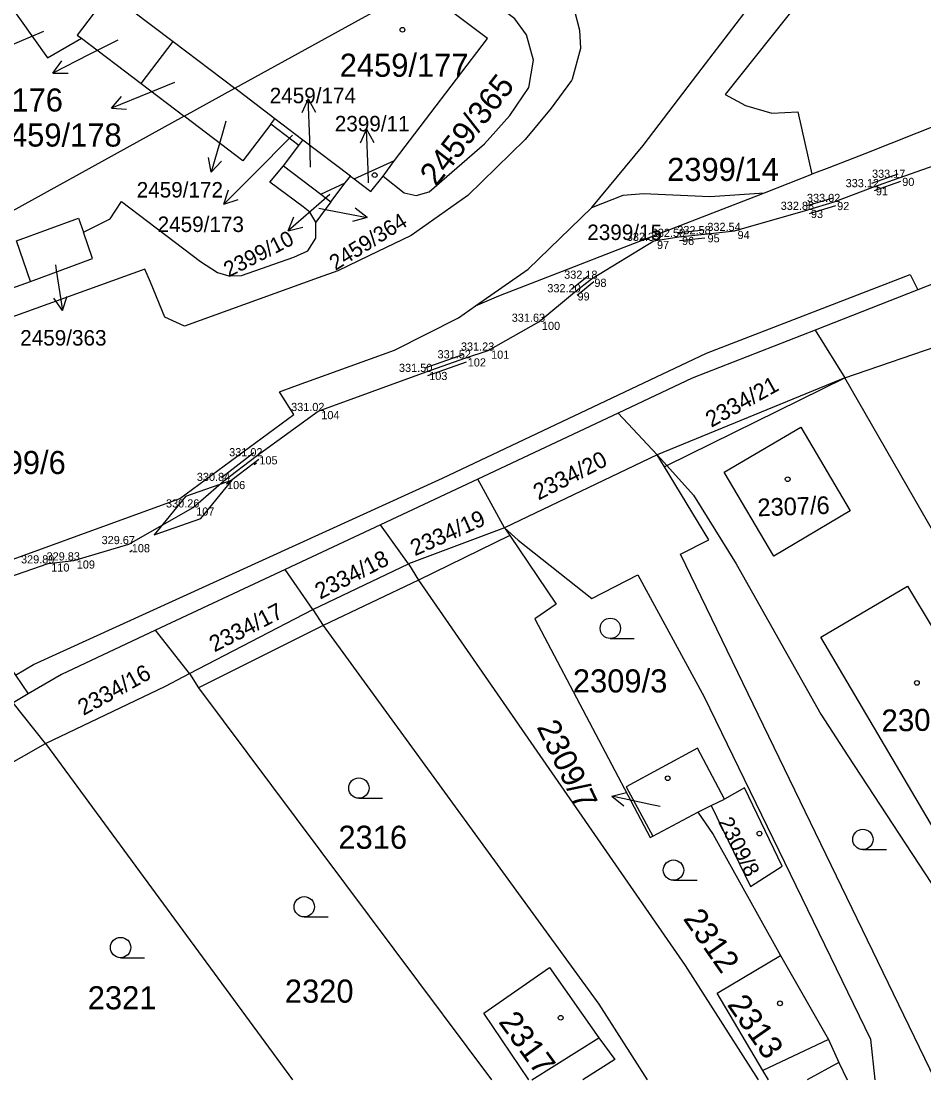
# Model space of a CAD drawing. Extents: x -606208 to -605570, y -1157873 to -1157573.
# Drawn here: x -605756.7 to -605690.3, y -1157764.5 to -1157686.5 of the extents above; entities that cross this region are included whole.
import ezdxf

# ---------------------------------------------------------------- set-up
doc = ezdxf.new("R2010")
doc.units = 0
for name, color, linetype in [('Vrstva 23', 7, 'Continuous'), ('Vrstva 30', 7, 'Continuous'), ('Vrstva 38', 7, 'Continuous'), ('Vrstva 58', 7, 'Continuous'), ('Vrstva 59', 7, 'Continuous'), ('Vrstva 60', 7, 'Continuous'), ('Vrstva 62', 7, 'Continuous'), ('Vrstva 7', 7, 'Continuous')]:
    doc.layers.add(name, color=color, linetype=linetype)

msp = doc.modelspace()

# ---------------------------------------------------------------- linework, layer by layer
at = {"layer": 'Vrstva 23'}
for p, q in [((-605739.593, -1157719.164), (-605739.429, -1157719.049)), ((-605748.587, -1157725.496), (-605748.751, -1157725.611))]:
    msp.add_line(p, q, dxfattribs=at)
msp.add_lwpolyline([(-605746.952, -1157724.345), (-605743.514, -1157723.148), (-605741.228, -1157720.315), (-605744.666, -1157721.512)], close=True, dxfattribs=at)
at = {"layer": 'Vrstva 30'}
msp.add_lwpolyline([(-605763.32, -1157729.43), (-605754.76, -1157726.45), (-605752.88, -1157726.23), (-605748.83, -1157725.03), (-605744.09, -1157722.33), (-605741.82, -1157720.38), (-605739.44, -1157718.56), (-605734.88, -1157715.23), (-605726.94, -1157712.35), (-605724.1, -1157711.35), (-605722.38, -1157710.78), (-605718.64, -1157708.66), (-605716.02, -1157706.49), (-605714.78, -1157705.49), (-605710.17, -1157702.7), (-605708.33, -1157702.41), (-605706.45, -1157702.21), (-605704.24, -1157701.97), (-605698.84, -1157700.42), (-605696.91, -1157699.84), (-605694.06, -1157698.75), (-605692.12, -1157698.06), (-605675.54, -1157692.21)], dxfattribs=at)
at = {"layer": 'Vrstva 38'}
for p, q in [((-605692.22, -1157697.78), (-605694.16, -1157698.47)), ((-605692.02, -1157698.34), (-605693.96, -1157699.03)), ((-605697, -1157699.55), (-605698.93, -1157700.13)), ((-605696.82, -1157700.13), (-605698.75, -1157700.71)), ((-605706.48, -1157701.91), (-605708.36, -1157702.11)), ((-605706.42, -1157702.51), (-605708.3, -1157702.71)), ((-605714.97, -1157705.26), (-605716.21, -1157706.26)), ((-605714.59, -1157705.72), (-605715.83, -1157706.72))]:
    msp.add_line(p, q, dxfattribs=at)
at = {"layer": 'Vrstva 60'}
for p, q in [((-605692.12, -1157698.06), (-605692.12, -1157698.06)), ((-605694.06, -1157698.75), (-605694.06, -1157698.75)), ((-605696.91, -1157699.84), (-605696.91, -1157699.84)), ((-605698.84, -1157700.42), (-605698.84, -1157700.42)), ((-605708.33, -1157702.41), (-605708.33, -1157702.41)), ((-605706.45, -1157702.21), (-605706.45, -1157702.21)), ((-605704.24, -1157701.97), (-605704.24, -1157701.97)), ((-605710.17, -1157702.7), (-605710.17, -1157702.7)), ((-605714.78, -1157705.49), (-605714.78, -1157705.49)), ((-605716.02, -1157706.49), (-605716.02, -1157706.49)), ((-605718.64, -1157708.66), (-605718.64, -1157708.66)), ((-605722.38, -1157710.78), (-605722.38, -1157710.78)), ((-605724.1, -1157711.35), (-605724.1, -1157711.35)), ((-605726.94, -1157712.35), (-605726.94, -1157712.35)), ((-605734.88, -1157715.23), (-605734.88, -1157715.23)), ((-605739.44, -1157718.56), (-605739.44, -1157718.56)), ((-605741.82, -1157720.38), (-605741.82, -1157720.38)), ((-605744.09, -1157722.33), (-605744.09, -1157722.33)), ((-605748.83, -1157725.03), (-605748.83, -1157725.03)), ((-605754.76, -1157726.45), (-605754.76, -1157726.45)), ((-605752.88, -1157726.23), (-605752.88, -1157726.23))]:
    msp.add_line(p, q, dxfattribs=at)
at = {"layer": 'Vrstva 62'}
for p, q in [((-605755.11, -1157687.29), (-605757.872, -1157688.463)), ((-605752.31, -1157687.79), (-605747.92, -1157691.12)), ((-605749.64, -1157687.93), (-605751.74, -1157688.99)), ((-605747.92, -1157691.12), (-605745.57, -1157688.03)), ((-605745.57, -1157688.03), (-605741.03, -1157691.47)), ((-605751.74, -1157688.99), (-605754.414, -1157690.352)), ((-605754.414, -1157690.352), (-605753.749, -1157689.452)), ((-605754.414, -1157690.352), (-605753.294, -1157690.344)), ((-605747.92, -1157691.12), (-605744.75, -1157693.52)), ((-605745.47, -1157691.04), (-605747.32, -1157691.8)), ((-605744.75, -1157693.52), (-605741.03, -1157691.47)), ((-605738.08, -1157693.71), (-605741.03, -1157691.47)), ((-605747.32, -1157691.8), (-605750.102, -1157692.924)), ((-605750.102, -1157692.924), (-605749.362, -1157692.085)), ((-605735.615, -1157692.251), (-605736.08, -1157693.269)), ((-605735.51, -1157695.25), (-605735.615, -1157692.251)), ((-605735.615, -1157692.251), (-605735.079, -1157693.234)), ((-605750.102, -1157692.924), (-605748.986, -1157693.013)), ((-605741.69, -1157693.9), (-605741.94, -1157694.77)), ((-605738.38, -1157694.11), (-605738.08, -1157693.71)), ((-605736.01, -1157695.28), (-605738.08, -1157693.71)), ((-605741.94, -1157694.77), (-605742.767, -1157697.655)), ((-605736.31, -1157695.68), (-605738.38, -1157694.11)), ((-605731.325, -1157694.481), (-605731.79, -1157695.499)), ((-605731.22, -1157697.48), (-605731.325, -1157694.481)), ((-605731.325, -1157694.481), (-605730.789, -1157695.464)), ((-605736.77, -1157694.93), (-605739.72, -1157697.88)), ((-605736.31, -1157695.68), (-605736.01, -1157695.28)), ((-605732.51, -1157697.94), (-605736.01, -1157695.28)), ((-605735.45, -1157697.27), (-605735.51, -1157695.25)), ((-605737.45, -1157697.18), (-605736.31, -1157695.68)), ((-605742.767, -1157697.655), (-605742.972, -1157696.554)), ((-605742.767, -1157697.655), (-605742.01, -1157696.83)), ((-605732.24, -1157698.14), (-605729.28, -1157696.78)), ((-605730.11, -1157697.93), (-605729.28, -1157696.78)), ((-605739.72, -1157697.88), (-605741.842, -1157700.002)), ((-605737.45, -1157697.18), (-605734.7, -1157699.27)), ((-605731.18, -1157698.43), (-605731.22, -1157697.48)), ((-605702.03, -1157699.16), (-605698.54, -1157697.8)), ((-605734.7, -1157699.27), (-605732.89, -1157698.44)), ((-605733.95, -1157699.84), (-605732.89, -1157698.44)), ((-605732.89, -1157698.44), (-605732.51, -1157697.94)), ((-605732.51, -1157697.94), (-605732.24, -1157698.14)), ((-605741.842, -1157700.002), (-605741.488, -1157698.94)), ((-605734.02, -1157699.3), (-605734.83, -1157700)), ((-605734.7, -1157699.27), (-605733.95, -1157699.84)), ((-605741.842, -1157700.002), (-605740.78, -1157699.648)), ((-605734.83, -1157700), (-605737.095, -1157701.969)), ((-605733.95, -1157699.84), (-605735.07, -1157701.32)), ((-605737.095, -1157701.969), (-605736.668, -1157700.934)), ((-605734.85, -1157700.29), (-605734.22, -1157700.41)), ((-605734.22, -1157700.41), (-605731.274, -1157700.983)), ((-605731.274, -1157700.983), (-605732.353, -1157701.283)), ((-605731.274, -1157700.983), (-605732.162, -1157700.3)), ((-605737.095, -1157701.969), (-605736.011, -1157701.69)), ((-605754.23, -1157704.47), (-605754.17, -1157704.87)), ((-605754.17, -1157704.87), (-605753.701, -1157707.834)), ((-605706.31, -1157710.96), (-605691.32, -1157705.17)), ((-605691.32, -1157705.17), (-605690.76, -1157706.31)), ((-605753.701, -1157707.834), (-605754.352, -1157706.923)), ((-605753.701, -1157707.834), (-605753.363, -1157706.767)), ((-605698.31, -1157709.27), (-605696.11, -1157712.79)), ((-605696.11, -1157712.79), (-605685.12, -1157708.99)), ((-605725.74, -1157720.17), (-605706.31, -1157710.96)), ((-605696.11, -1157712.79), (-605709.94, -1157718.45)), ((-605709.22, -1157719.25), (-605696.11, -1157712.79)), ((-605712.81, -1157715.38), (-605723.14, -1157720.24)), ((-605709.94, -1157718.45), (-605712.81, -1157715.38)), ((-605709.94, -1157718.45), (-605721.17, -1157723.83)), ((-605709.94, -1157718.45), (-605709.22, -1157719.25)), ((-605709.4, -1157719.34), (-605709.22, -1157719.25)), ((-605755.85, -1157733.9), (-605725.74, -1157720.17)), ((-605723.14, -1157720.24), (-605730.29, -1157723.6)), ((-605721.17, -1157723.83), (-605723.14, -1157720.24)), ((-605730.29, -1157723.6), (-605737.31, -1157726.9)), ((-605728.24, -1157726.49), (-605730.29, -1157723.6)), ((-605721.17, -1157723.83), (-605728.24, -1157726.49)), ((-605721.17, -1157723.83), (-605720.17, -1157724.75)), ((-605720.78, -1157724.4), (-605727.5, -1157727.68)), ((-605735.27, -1157729.85), (-605728.24, -1157726.49)), ((-605737.31, -1157726.9), (-605746.85, -1157731.37)), ((-605735.27, -1157729.85), (-605737.31, -1157726.9)), ((-605727.5, -1157727.68), (-605734.53, -1157731.01)), ((-605691.51, -1157728.12), (-605689.63, -1157731.27)), ((-605744.35, -1157734.56), (-605735.27, -1157729.85)), ((-605744.35, -1157734.56), (-605746.85, -1157731.37)), ((-605734.53, -1157731.01), (-605743.69, -1157735.6)), ((-605713.383, -1157731.98), (-605711.633, -1157731.98)), ((-605757.17, -1157734.67), (-605755.85, -1157733.9)), ((-605756.23, -1157736.06), (-605757.35, -1157736.71)), ((-605754.95, -1157739.7), (-605757.35, -1157736.71)), ((-605766.71, -1157746.36), (-605754.95, -1157739.7)), ((-605731.893, -1157743.74), (-605730.143, -1157743.74)), ((-605713.265, -1157743.596), (-605712.182, -1157743.314)), ((-605710.33, -1157744.22), (-605713.265, -1157743.596)), ((-605713.265, -1157743.596), (-605712.39, -1157744.294)), ((-605705.96, -1157744.28), (-605704.98, -1157743.8)), ((-605709.71, -1157744.35), (-605710.33, -1157744.22)), ((-605706.95, -1157744.76), (-605705.96, -1157744.28)), ((-605710.25, -1157746.53), (-605706.95, -1157744.76)), ((-605694.793, -1157747.52), (-605693.043, -1157747.52)), ((-605708.733, -1157749.78), (-605706.983, -1157749.78)), ((-605735.913, -1157752.48), (-605734.163, -1157752.48)), ((-605749.433, -1157755.48), (-605747.683, -1157755.48)), ((-605719.15, -1157764.47), (-605714.24, -1157761.37)), ((-605697.33, -1157761.51), (-605702.15, -1157763.78)), ((-605696.57, -1157763.2), (-605695.95, -1157764.47))]:
    msp.add_line(p, q, dxfattribs=at)
for points in [[(-605714.75, -1157700.25), (-605710.96, -1157695.68), (-605710.18, -1157694.65), (-605706.94, -1157690.4), (-605702.43, -1157684.48), (-605699.9, -1157681.15), (-605696.13, -1157676.2), (-605691.65, -1157670.31), (-605690.12, -1157670.1), (-605687.04, -1157672.45), (-605682.78, -1157666.84), (-605681.4, -1157665.03), (-605679.37, -1157662.36), (-605660.55, -1157637.61), (-605653.28, -1157627.99)], [(-605694.7, -1157678.73), (-605697.05, -1157682.01), (-605704.94, -1157691.92), (-605703.43, -1157692.73), (-605701.49, -1157693.29), (-605699.59, -1157693.2), (-605698.54, -1157697.8)], [(-605730.11, -1157697.93), (-605728.55, -1157699.16), (-605727.68, -1157699.35), (-605726.72, -1157699.08), (-605722.65, -1157695.57), (-605720.78, -1157693.46), (-605719.38, -1157691.41), (-605719.05, -1157689.39), (-605719.55, -1157687.53), (-605720.4, -1157686.35), (-605728.5, -1157680.23), (-605729.94, -1157682.1)], [(-605760, -1157681.95), (-605754.81, -1157689.23), (-605752.31, -1157687.79)], [(-605750.28, -1157684.46), (-605748.66, -1157685.69), (-605745.57, -1157688.03)], [(-605741.03, -1157691.47), (-605728.21, -1157684.4), (-605727.42, -1157684.02)], [(-605729.28, -1157696.78), (-605722.43, -1157687.81), (-605727.42, -1157684.02)], [(-605750.58, -1157684.86), (-605752.62, -1157687.55), (-605752.31, -1157687.79)], [(-605716.01, -1157685.76), (-605715.64, -1157687.2), (-605715.58, -1157688.54), (-605716.2, -1157690.79), (-605716.23, -1157690.9), (-605717.74, -1157692.92), (-605719.64, -1157695.24), (-605723.87, -1157699.35), (-605728.04, -1157702.31), (-605731.16, -1157703.8), (-605733.45, -1157704.9), (-605734.89, -1157705.42), (-605744.73, -1157708.97), (-605746.18, -1157708.32), (-605747.24, -1157705.75), (-605747.64, -1157704.79), (-605761.33, -1157709.71), (-605760.16, -1157713.04)], [(-605683.3, -1157691.79), (-605694.65, -1157696.29), (-605697.29, -1157697.32), (-605698.54, -1157697.8)], [(-605744.75, -1157693.52), (-605778.05, -1157711.9), (-605782.37, -1157714.52)], [(-605738.38, -1157694.11), (-605740.43, -1157696.8), (-605744.75, -1157693.52)], [(-605735.07, -1157701.32), (-605735.49, -1157700.58), (-605736, -1157700.19), (-605738.44, -1157698.39), (-605737.45, -1157697.18)], [(-605732.24, -1157698.14), (-605731.02, -1157699.07), (-605730.11, -1157697.93)], [(-605723.31, -1157707.49), (-605721.58, -1157706.75), (-605716.45, -1157704.75), (-605712.81, -1157703.34), (-605702.03, -1157699.16)], [(-605714.75, -1157700.25), (-605712.44, -1157699.33), (-605710.93, -1157699.21), (-605706.06, -1157699.44), (-605702.03, -1157699.16)], [(-605752.17, -1157702.07), (-605750.2, -1157701.08), (-605749.36, -1157699.81), (-605743.54, -1157704.22), (-605742.3, -1157705.04), (-605741.46, -1157705.28), (-605740.53, -1157705.25), (-605736.69, -1157703.9), (-605735.65, -1157703.44), (-605735.06, -1157702.51), (-605735.07, -1157701.32)], [(-605673.75, -1157699.63), (-605690.76, -1157706.31), (-605698.31, -1157709.27)], [(-605723.31, -1157707.49), (-605719.42, -1157704.78), (-605714.75, -1157700.25)], [(-605756.06, -1157705.69), (-605757.1, -1157702.71), (-605752.53, -1157701.03), (-605752.17, -1157702.07)], [(-605756.06, -1157705.69), (-605751.49, -1157704.01), (-605752.17, -1157702.07)], [(-605782.37, -1157714.52), (-605781.95, -1157714.66), (-605781, -1157714.58), (-605756.06, -1157705.69)], [(-605761.94, -1157727.8), (-605745.07, -1157721.67), (-605736.69, -1157715.48), (-605737.67, -1157713.93), (-605737.74, -1157713.82), (-605736.68, -1157713.43), (-605729.27, -1157710.74), (-605724.56, -1157708.36), (-605723.31, -1157707.49)], [(-605698.31, -1157709.27), (-605707.35, -1157712.82), (-605712.81, -1157715.38)], [(-605666.05, -1157763.97), (-605686.49, -1157729.56), (-605696.11, -1157712.79)], [(-605699.37, -1157716.42), (-605695.72, -1157722.57), (-605701.34, -1157725.92), (-605705, -1157719.74), (-605699.37, -1157716.42)], [(-605706.14, -1157724.71), (-605709.4, -1157719.34), (-605709.94, -1157718.45)], [(-605709.22, -1157719.25), (-605707.25, -1157721.43), (-605704.12, -1157726.49), (-605697.88, -1157737.54)], [(-605721.17, -1157723.83), (-605720.78, -1157724.4), (-605717.36, -1157729.44)], [(-605720.17, -1157724.75), (-605714.74, -1157729.03), (-605711.35, -1157727.3), (-605706.48, -1157736.27), (-605694.23, -1157761.47), (-605693.92, -1157764.47)], [(-605689.48, -1157764.47), (-605708.22, -1157725.77), (-605706.14, -1157724.71)], [(-605728.24, -1157726.49), (-605727.5, -1157727.68), (-605707.88, -1157756.06), (-605702.51, -1157764.47)], [(-605761.94, -1157727.8), (-605757.17, -1157734.67), (-605756.23, -1157736.06)], [(-605682.82, -1157742.68), (-605689.26, -1157746.54), (-605697.9, -1157731.89), (-605691.51, -1157728.12)], [(-605735.27, -1157729.85), (-605734.53, -1157731.01), (-605714.23, -1157758.91), (-605710.66, -1157764.47)], [(-605717.36, -1157729.44), (-605718.94, -1157730.53), (-605710.45, -1157746.64), (-605710.25, -1157746.53)], [(-605746.85, -1157731.37), (-605753.78, -1157734.63), (-605756.23, -1157736.06)], [(-605754.95, -1157739.7), (-605746.12, -1157735.48), (-605744.35, -1157734.56)], [(-605744.35, -1157734.56), (-605743.69, -1157735.6), (-605722.14, -1157764.47)], [(-605697.88, -1157737.54), (-605695.91, -1157740.61), (-605680.26, -1157764.47)], [(-605754.95, -1157739.7), (-605736.78, -1157764.47)], [(-605704.98, -1157743.8), (-605706.96, -1157740.06), (-605712.21, -1157742.89), (-605710.25, -1157746.53)], [(-605705.96, -1157744.28), (-605703.07, -1157750.23), (-605700.73, -1157748.74), (-605703.51, -1157742.98), (-605704.98, -1157743.8)], [(-605706.95, -1157744.76), (-605705.82, -1157746.42), (-605700.86, -1157755.32)], [(-605701.75, -1157764.47), (-605702.15, -1157763.78), (-605705.52, -1157758.1), (-605700.86, -1157755.32)], [(-605700.86, -1157755.32), (-605697.33, -1157761.51), (-605696.57, -1157763.2)], [(-605719.39, -1157764.47), (-605722.69, -1157759.56), (-605717.86, -1157756.19)], [(-605717.86, -1157756.19), (-605714.24, -1157761.37), (-605713.06, -1157762.98), (-605715.4, -1157764.47)], [(-605696.57, -1157763.2), (-605698.9, -1157764.47)]]:
    msp.add_lwpolyline(points, dxfattribs=at)
for centre, radius in [((-605728.687, -1157687.159), 0.175), ((-605730.727, -1157697.859), 0.175), ((-605700.327, -1157720.249), 0.175), ((-605713.383, -1157731.23), 0.75), ((-605690.817, -1157735.249), 0.175), ((-605731.893, -1157742.99), 0.75), ((-605709.157, -1157742.269), 0.175), ((-605702.407, -1157746.339), 0.175), ((-605694.793, -1157746.77), 0.75), ((-605708.733, -1157749.03), 0.75), ((-605735.913, -1157751.73), 0.75), ((-605749.433, -1157754.73), 0.75), ((-605700.897, -1157758.839), 0.175), ((-605717.037, -1157759.899), 0.175)]:
    msp.add_circle(centre, radius, dxfattribs=at)
at = {"layer": 'Vrstva 7'}
for p, q in [((-605724.2, -1157711.07), (-605727.04, -1157712.07)), ((-605724, -1157711.63), (-605726.84, -1157712.63)), ((-605739.62, -1157718.32), (-605742, -1157720.14)), ((-605739.26, -1157718.8), (-605741.64, -1157720.62))]:
    msp.add_line(p, q, dxfattribs=at)

# ---------------------------------------------------------------- texts
at = {"layer": 'Vrstva 58'}
for s, p in [('333.17 ', (-605694.12, -1157698.06)), ('333.12 ', (-605696.06, -1157698.75)), ('333.02 ', (-605698.91, -1157699.84)), ('332.88 ', (-605700.84, -1157700.42)), ('332.58 ', (-605708.45, -1157702.21)), ('332.54 ', (-605706.24, -1157701.97)), ('332.33 ', (-605712.17, -1157702.7)), ('332.50 ', (-605710.33, -1157702.41)), ('332.18 ', (-605716.78, -1157705.49)), ('332.20 ', (-605718.02, -1157706.49)), ('331.63 ', (-605720.64, -1157708.66)), ('331.23 ', (-605724.38, -1157710.78)), ('331.52 ', (-605726.1, -1157711.35)), ('331.50 ', (-605728.94, -1157712.35)), ('331.02 ', (-605736.88, -1157715.23)), ('331.02 ', (-605741.44, -1157718.56)), ('330.84 ', (-605743.82, -1157720.38)), ('330.26 ', (-605746.09, -1157722.33)), ('329.67 ', (-605750.83, -1157725.03)), ('329.89 ', (-605756.76, -1157726.45)), ('329.83 ', (-605754.88, -1157726.23))]:
    msp.add_text(s, height=0.6, dxfattribs=at).set_placement(p)
at = {"layer": 'Vrstva 59'}
for s, p in [(' 90', (-605692.12, -1157698.66)), (' 91', (-605694.06, -1157699.35)), (' 92', (-605696.91, -1157700.44)), (' 93', (-605698.84, -1157701.02)), (' 96', (-605708.33, -1157703.01)), (' 95', (-605706.45, -1157702.81)), (' 94', (-605704.24, -1157702.57)), (' 97', (-605710.17, -1157703.3)), (' 98', (-605714.78, -1157706.09)), (' 99', (-605716.02, -1157707.09)), (' 100', (-605718.64, -1157709.26)), (' 101', (-605722.38, -1157711.38)), (' 102', (-605724.1, -1157711.95)), (' 103', (-605726.94, -1157712.95)), (' 104', (-605734.88, -1157715.83)), (' 105', (-605739.44, -1157719.16)), (' 106', (-605741.82, -1157720.98)), (' 107', (-605744.09, -1157722.93)), (' 108', (-605748.83, -1157725.63)), (' 110', (-605754.76, -1157727.05)), (' 109', (-605752.88, -1157726.83))]:
    msp.add_text(s, height=0.6, dxfattribs=at).set_placement(p)
at = {"layer": 'Vrstva 62'}
for s, height, p in [('2459/177', 1.7, (-605733.303, -1157690.62)), ('2459/176', 1.7, (-605763.157, -1157693.18)), ('2459/174', 1.139, (-605738.456, -1157692.57)), ('2459/178', 1.7, (-605758.837, -1157695.76)), ('2399/11', 1.139, (-605733.665, -1157694.64)), ('2399/14', 1.7, (-605709.2, -1157698.29)), ('2459/172', 1.139, (-605748.246, -1157699.51)), ('2459/173', 1.139, (-605746.705, -1157702.05)), ('2399/15', 1.139, (-605715.08, -1157702.64)), ('2459/363', 1.139, (-605756.82, -1157710.409)), ('2399/6', 1.7, (-605760.42, -1157719.87)), ('2309/3', 1.7, (-605716.14, -1157735.95)), ('2316', 1.7, (-605733.4, -1157747.46)), ('2320', 1.7, (-605737.34, -1157758.79)), ('2321', 1.7, (-605751.85, -1157759.28))]:
    msp.add_text(s, height=height, dxfattribs=at).set_placement(p)
for s, height, rotation, p in [('2459/365', 1.7, 52, (-605726.2, -1157698.77)), ('2459/364', 1.139, 32, (-605733.614, -1157704.917)), ('2399/10', 1.139, 27, (-605741.477, -1157705.405)), ('2334/21', 1.2, 29, (-605705.95, -1157716.47)), ('2334/20', 1.2, 27, (-605718.67, -1157721.82)), ('2307/6', 1.3, 2, (-605702.533, -1157722.984)), ('2334/19', 1.2, 24, (-605727.77, -1157725.93)), ('2334/18', 1.2, 27, (-605734.74, -1157729.12)), ('2334/17', 1.2, 27, (-605742.52, -1157733.01)), ('2334/16', 1.2, 29, (-605752.16, -1157737.68)), ('2307/5', 1.618, 1, (-605693.408, -1157738.832)), ('2309/7', 1.7, 296, (-605718.833, -1157738.485)), ('2309/8', 1.139, 297, (-605705.467, -1157745.475)), ('2312', 1.7, 305, (-605708.07, -1157752.61)), ('2313', 1.7, 305, (-605704.83, -1157758.94)), ('2317', 1.7, 306, (-605721.66, -1157760.21))]:
    msp.add_text(s, height=height, rotation=rotation, dxfattribs=at).set_placement(p)

doc.saveas('drawing.dxf')
